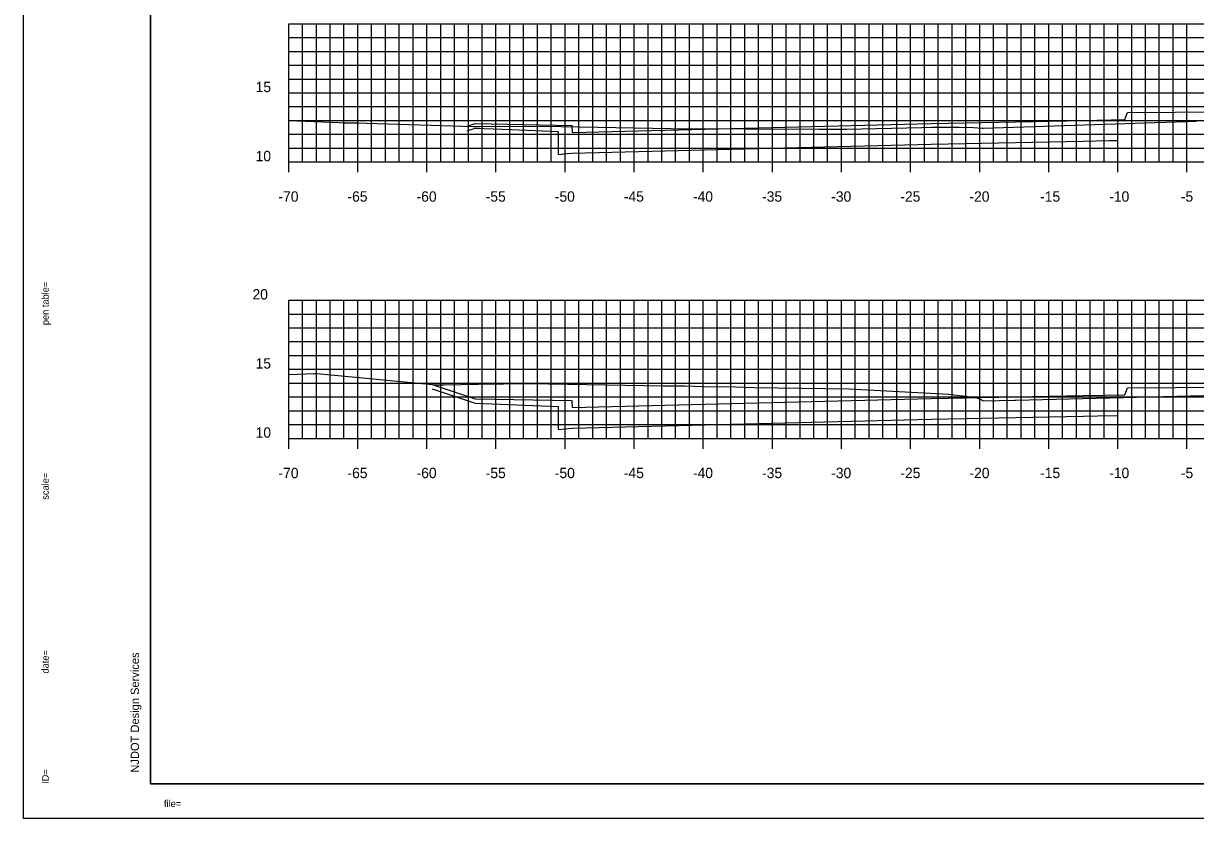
# Model space of a CAD drawing. Extents: x 40011 to 50684, y 49949 to 72236.
# Drawn here: x 41889.7 to 41974.5, y 68071.1 to 68128.6 of the extents above; entities that cross this region are included whole.
import ezdxf

# ---------------------------------------------------------------- set-up
doc = ezdxf.new("R2010")
doc.units = 0
for name, color, linetype in [('1', 7, 'Continuous'), ('41', 7, 'Continuous'), ('51', 7, 'Continuous'), ('52', 7, 'Continuous'), ('53', 7, 'Continuous'), ('54', 7, 'Continuous'), ('55', 7, 'Continuous'), ('57', 7, 'Continuous'), ('58', 7, 'Continuous'), ('59', 7, 'Continuous')]:
    doc.layers.add(name, color=color, linetype=linetype)

msp = doc.modelspace()

# ---------------------------------------------------------------- linework, layer by layer
at = {"layer": '1'}
for p, q in [((41898.891, 68178.597), (41898.891, 68073.597)), ((41898.891, 68073.597), (42063.891, 68073.597)), ((42064.392, 68071.097), (41889.697, 68071.097))]:
    msp.add_line(p, q, dxfattribs=at)
at = {"layer": '41'}
for points in [[(41889.697, 68181.097), (42064.392, 68181.097), (42064.392, 68071.097), (41889.697, 68071.097)], [(41898.891, 68178.597), (42063.891, 68178.597), (42063.891, 68073.597), (41898.891, 68073.597)]]:
    msp.add_lwpolyline(points, close=True, dxfattribs=at)
at = {"layer": '51'}
for p, q in [((41908.891, 68118.597), (41908.891, 68128.597)), ((41908.891, 68128.597), (41909.641, 68128.597)), ((41908.891, 68123.597), (41909.641, 68123.597)), ((41908.891, 68118.597), (41909.641, 68118.597)), ((41908.891, 68098.597), (41908.891, 68108.597)), ((41908.891, 68108.597), (41909.641, 68108.597)), ((41908.891, 68103.597), (41909.641, 68103.597)), ((41908.891, 68098.597), (41909.641, 68098.597))]:
    msp.add_line(p, q, dxfattribs=at)
at = {"layer": '52'}
for p, q in [((41908.891, 68118.597), (42048.891, 68118.597)), ((41908.891, 68117.847), (41908.891, 68118.597)), ((41913.891, 68117.847), (41913.891, 68118.597)), ((41918.891, 68117.847), (41918.891, 68118.597)), ((41923.891, 68117.847), (41923.891, 68118.597)), ((41928.891, 68117.847), (41928.891, 68118.597)), ((41933.891, 68117.847), (41933.891, 68118.597)), ((41938.891, 68117.847), (41938.891, 68118.597)), ((41943.891, 68117.847), (41943.891, 68118.597)), ((41948.891, 68117.847), (41948.891, 68118.597)), ((41953.891, 68117.847), (41953.891, 68118.597)), ((41958.891, 68117.847), (41958.891, 68118.597)), ((41963.891, 68117.847), (41963.891, 68118.597)), ((41968.891, 68117.847), (41968.891, 68118.597)), ((41973.891, 68117.847), (41973.891, 68118.597)), ((41908.891, 68098.597), (42048.891, 68098.597)), ((41908.891, 68097.847), (41908.891, 68098.597)), ((41913.891, 68097.847), (41913.891, 68098.597)), ((41918.891, 68097.847), (41918.891, 68098.597)), ((41923.891, 68097.847), (41923.891, 68098.597)), ((41928.891, 68097.847), (41928.891, 68098.597)), ((41933.891, 68097.847), (41933.891, 68098.597)), ((41938.891, 68097.847), (41938.891, 68098.597)), ((41943.891, 68097.847), (41943.891, 68098.597)), ((41948.891, 68097.847), (41948.891, 68098.597)), ((41953.891, 68097.847), (41953.891, 68098.597)), ((41958.891, 68097.847), (41958.891, 68098.597)), ((41963.891, 68097.847), (41963.891, 68098.597)), ((41968.891, 68097.847), (41968.891, 68098.597)), ((41973.891, 68097.847), (41973.891, 68098.597))]:
    msp.add_line(p, q, dxfattribs=at)
at = {"layer": '53'}
for p, q in [((41908.891, 68127.597), (42048.891, 68127.597)), ((41908.891, 68126.597), (42048.891, 68126.597)), ((41908.891, 68125.597), (42048.891, 68125.597)), ((41908.891, 68124.597), (42048.891, 68124.597)), ((41908.891, 68122.597), (42048.891, 68122.597)), ((41908.891, 68121.597), (42048.891, 68121.597)), ((41908.891, 68120.597), (42048.891, 68120.597)), ((41908.891, 68119.597), (42048.891, 68119.597)), ((41908.891, 68107.597), (42048.891, 68107.597)), ((41908.891, 68106.597), (42048.891, 68106.597)), ((41908.891, 68105.597), (42048.891, 68105.597)), ((41908.891, 68104.597), (42048.891, 68104.597)), ((41908.891, 68102.597), (42048.891, 68102.597)), ((41908.891, 68101.597), (42048.891, 68101.597)), ((41908.891, 68100.597), (42048.891, 68100.597)), ((41908.891, 68099.597), (42048.891, 68099.597))]:
    msp.add_line(p, q, dxfattribs=at)
at = {"layer": '54'}
for p, q in [((41909.891, 68118.597), (41909.891, 68128.597)), ((41910.891, 68118.597), (41910.891, 68128.597)), ((41911.891, 68118.597), (41911.891, 68128.597)), ((41912.891, 68118.597), (41912.891, 68128.597)), ((41914.891, 68118.597), (41914.891, 68128.597)), ((41915.891, 68118.597), (41915.891, 68128.597)), ((41916.891, 68118.597), (41916.891, 68128.597)), ((41917.891, 68118.597), (41917.891, 68128.597)), ((41919.891, 68118.597), (41919.891, 68128.597)), ((41920.891, 68118.597), (41920.891, 68128.597)), ((41921.891, 68118.597), (41921.891, 68128.597)), ((41922.891, 68118.597), (41922.891, 68128.597)), ((41924.891, 68118.597), (41924.891, 68128.597)), ((41925.891, 68118.597), (41925.891, 68128.597)), ((41926.891, 68118.597), (41926.891, 68128.597)), ((41927.891, 68118.597), (41927.891, 68128.597)), ((41929.891, 68118.597), (41929.891, 68128.597)), ((41930.891, 68118.597), (41930.891, 68128.597)), ((41931.891, 68118.597), (41931.891, 68128.597)), ((41932.891, 68118.597), (41932.891, 68128.597)), ((41934.891, 68118.597), (41934.891, 68128.597)), ((41935.891, 68118.597), (41935.891, 68128.597)), ((41936.891, 68118.597), (41936.891, 68128.597)), ((41937.891, 68118.597), (41937.891, 68128.597)), ((41939.891, 68118.597), (41939.891, 68128.597)), ((41940.891, 68118.597), (41940.891, 68128.597)), ((41941.891, 68118.597), (41941.891, 68128.597)), ((41942.891, 68118.597), (41942.891, 68128.597)), ((41944.891, 68118.597), (41944.891, 68128.597)), ((41945.891, 68118.597), (41945.891, 68128.597)), ((41946.891, 68118.597), (41946.891, 68128.597)), ((41947.891, 68118.597), (41947.891, 68128.597)), ((41949.891, 68118.597), (41949.891, 68128.597)), ((41950.891, 68118.597), (41950.891, 68128.597)), ((41951.891, 68118.597), (41951.891, 68128.597)), ((41952.891, 68118.597), (41952.891, 68128.597)), ((41954.891, 68118.597), (41954.891, 68128.597)), ((41955.891, 68118.597), (41955.891, 68128.597)), ((41956.891, 68118.597), (41956.891, 68128.597)), ((41957.891, 68118.597), (41957.891, 68128.597)), ((41959.891, 68118.597), (41959.891, 68128.597)), ((41960.891, 68118.597), (41960.891, 68128.597)), ((41961.891, 68118.597), (41961.891, 68128.597)), ((41962.891, 68118.597), (41962.891, 68128.597)), ((41964.891, 68118.597), (41964.891, 68128.597)), ((41965.891, 68118.597), (41965.891, 68128.597)), ((41966.891, 68118.597), (41966.891, 68128.597)), ((41967.891, 68118.597), (41967.891, 68128.597)), ((41969.891, 68118.597), (41969.891, 68128.597)), ((41970.891, 68118.597), (41970.891, 68128.597)), ((41971.891, 68118.597), (41971.891, 68128.597)), ((41972.891, 68118.597), (41972.891, 68128.597)), ((41909.891, 68098.597), (41909.891, 68108.597)), ((41910.891, 68098.597), (41910.891, 68108.597)), ((41911.891, 68098.597), (41911.891, 68108.597)), ((41912.891, 68098.597), (41912.891, 68108.597)), ((41914.891, 68098.597), (41914.891, 68108.597)), ((41915.891, 68098.597), (41915.891, 68108.597)), ((41916.891, 68098.597), (41916.891, 68108.597)), ((41917.891, 68098.597), (41917.891, 68108.597)), ((41919.891, 68098.597), (41919.891, 68108.597)), ((41920.891, 68098.597), (41920.891, 68108.597)), ((41921.891, 68098.597), (41921.891, 68108.597)), ((41922.891, 68098.597), (41922.891, 68108.597)), ((41924.891, 68098.597), (41924.891, 68108.597)), ((41925.891, 68098.597), (41925.891, 68108.597)), ((41926.891, 68098.597), (41926.891, 68108.597)), ((41927.891, 68098.597), (41927.891, 68108.597)), ((41929.891, 68098.597), (41929.891, 68108.597)), ((41930.891, 68098.597), (41930.891, 68108.597)), ((41931.891, 68098.597), (41931.891, 68108.597)), ((41932.891, 68098.597), (41932.891, 68108.597)), ((41934.891, 68098.597), (41934.891, 68108.597)), ((41935.891, 68098.597), (41935.891, 68108.597)), ((41936.891, 68098.597), (41936.891, 68108.597)), ((41937.891, 68098.597), (41937.891, 68108.597)), ((41939.891, 68098.597), (41939.891, 68108.597)), ((41940.891, 68098.597), (41940.891, 68108.597)), ((41941.891, 68098.597), (41941.891, 68108.597)), ((41942.891, 68098.597), (41942.891, 68108.597)), ((41944.891, 68098.597), (41944.891, 68108.597)), ((41945.891, 68098.597), (41945.891, 68108.597)), ((41946.891, 68098.597), (41946.891, 68108.597)), ((41947.891, 68098.597), (41947.891, 68108.597)), ((41949.891, 68098.597), (41949.891, 68108.597)), ((41950.891, 68098.597), (41950.891, 68108.597)), ((41951.891, 68098.597), (41951.891, 68108.597)), ((41952.891, 68098.597), (41952.891, 68108.597)), ((41954.891, 68098.597), (41954.891, 68108.597)), ((41955.891, 68098.597), (41955.891, 68108.597)), ((41956.891, 68098.597), (41956.891, 68108.597)), ((41957.891, 68098.597), (41957.891, 68108.597)), ((41959.891, 68098.597), (41959.891, 68108.597)), ((41960.891, 68098.597), (41960.891, 68108.597)), ((41961.891, 68098.597), (41961.891, 68108.597)), ((41962.891, 68098.597), (41962.891, 68108.597)), ((41964.891, 68098.597), (41964.891, 68108.597)), ((41965.891, 68098.597), (41965.891, 68108.597)), ((41966.891, 68098.597), (41966.891, 68108.597)), ((41967.891, 68098.597), (41967.891, 68108.597)), ((41969.891, 68098.597), (41969.891, 68108.597)), ((41970.891, 68098.597), (41970.891, 68108.597)), ((41971.891, 68098.597), (41971.891, 68108.597)), ((41972.891, 68098.597), (41972.891, 68108.597))]:
    msp.add_line(p, q, dxfattribs=at)
at = {"layer": '55'}
for p, q in [((41908.891, 68128.597), (42048.891, 68128.597)), ((41908.891, 68118.597), (41908.891, 68128.597)), ((41913.891, 68118.597), (41913.891, 68128.597)), ((41918.891, 68118.597), (41918.891, 68128.597)), ((41923.891, 68118.597), (41923.891, 68128.597)), ((41928.891, 68118.597), (41928.891, 68128.597)), ((41933.891, 68118.597), (41933.891, 68128.597)), ((41938.891, 68118.597), (41938.891, 68128.597)), ((41943.891, 68118.597), (41943.891, 68128.597)), ((41948.891, 68118.597), (41948.891, 68128.597)), ((41953.891, 68118.597), (41953.891, 68128.597)), ((41958.891, 68118.597), (41958.891, 68128.597)), ((41963.891, 68118.597), (41963.891, 68128.597)), ((41968.891, 68118.597), (41968.891, 68128.597)), ((41973.891, 68118.597), (41973.891, 68128.597)), ((41908.891, 68123.597), (42048.891, 68123.597)), ((41908.891, 68118.597), (42048.891, 68118.597)), ((41908.891, 68108.597), (42048.891, 68108.597)), ((41908.891, 68098.597), (41908.891, 68108.597)), ((41913.891, 68098.597), (41913.891, 68108.597)), ((41918.891, 68098.597), (41918.891, 68108.597)), ((41923.891, 68098.597), (41923.891, 68108.597)), ((41928.891, 68098.597), (41928.891, 68108.597)), ((41933.891, 68098.597), (41933.891, 68108.597)), ((41938.891, 68098.597), (41938.891, 68108.597)), ((41943.891, 68098.597), (41943.891, 68108.597)), ((41948.891, 68098.597), (41948.891, 68108.597)), ((41953.891, 68098.597), (41953.891, 68108.597)), ((41958.891, 68098.597), (41958.891, 68108.597)), ((41963.891, 68098.597), (41963.891, 68108.597)), ((41968.891, 68098.597), (41968.891, 68108.597)), ((41973.891, 68098.597), (41973.891, 68108.597)), ((41908.891, 68103.597), (42048.891, 68103.597)), ((41908.891, 68098.597), (42048.891, 68098.597))]:
    msp.add_line(p, q, dxfattribs=at)
at = {"layer": '57'}
for points in [[(41908.891, 68121.607), (41912.549, 68121.441), (41912.797, 68121.438), (41913.222, 68121.432), (41913.972, 68121.421), (41914.532, 68121.412), (41922.258, 68121.162), (41922.449, 68121.159), (41922.757, 68121.155), (41927.284, 68121.175), (41936.544, 68121.019), (41947.26, 68120.967), (41949.249, 68120.966), (41954.711, 68121.095), (41955.427, 68121.11), (41955.84, 68121.113), (41956.519, 68121.116), (41957.412, 68121.106), (41958.436, 68121.091), (41959.064, 68121.039), (41959.153, 68121.029), (41974.554, 68121.546)], [(41908.891, 68103.214), (41910.747, 68103.299), (41910.96, 68103.29), (41919.544, 68102.48), (41920.148, 68102.482), (41922.608, 68102.517), (41926.315, 68102.579), (41935.991, 68102.41), (41937.099, 68102.401), (41937.566, 68102.394), (41938.273, 68102.38), (41938.923, 68102.362), (41941.236, 68102.323), (41942.57, 68102.282), (41949.44, 68102.175), (41956.204, 68101.825), (41956.63, 68101.809), (41958.25, 68101.605), (41958.548, 68101.584), (41958.556, 68101.585), (41959.031, 68101.377), (41959.036, 68101.375), (41959.037, 68101.374), (41959.19, 68101.307), (41961.41, 68101.361), (41961.496, 68101.363), (41980.931, 68101.835)]]:
    msp.add_lwpolyline(points, dxfattribs=at)
at = {"layer": '58'}
for points in [[(41921.796, 68120.847), (41921.938, 68120.894), (41922.382, 68121.042), (41924.978, 68120.94), (41928.386, 68120.807), (41928.396, 68119.138), (41929.029, 68119.197), (41929.391, 68119.231), (41955.391, 68119.881), (41966.391, 68120.101), (41968.285, 68120.139), (41968.891, 68120.151)], [(41919.277, 68102.175), (41920.36, 68101.814), (41922.381, 68101.14), (41928.386, 68100.904), (41928.391, 68100.05), (41928.396, 68099.235), (41929.392, 68099.329), (41955.391, 68099.979), (41966.392, 68100.199), (41966.406, 68100.199), (41967.421, 68100.22), (41968.891, 68100.249)]]:
    msp.add_lwpolyline(points, dxfattribs=at)
at = {"layer": '59'}
for points in [[(41921.796, 68121.177), (41922.382, 68121.372), (41929.382, 68121.232), (41929.392, 68120.732), (41955.392, 68121.382), (41966.392, 68121.602), (41969.391, 68121.662), (41969.582, 68122.164), (41976.506, 68122.217), (41981.202, 68122.254), (41981.391, 68121.755), (41984.392, 68121.71), (41995.392, 68121.49), (42010.392, 68121.115), (42010.402, 68121.615), (42017.402, 68121.755), (42017.69, 68121.851)], [(41919.276, 68102.505), (41922.382, 68101.47), (41929.382, 68101.33), (41929.392, 68100.83), (41955.392, 68101.48), (41966.392, 68101.7), (41969.391, 68101.76), (41969.582, 68102.261), (41976.506, 68102.315), (41981.202, 68102.351), (41981.391, 68101.852), (41984.392, 68101.807), (41995.392, 68101.587), (42010.392, 68101.212), (42010.402, 68101.712), (42017.402, 68101.852), (42017.513, 68101.889)]]:
    msp.add_lwpolyline(points, dxfattribs=at)

# ---------------------------------------------------------------- texts
at = {"layer": '1'}
for s, height, rotation, p in [('...................pentable..................', 0.0072, 90, (41891.529, 68110.775)), ('pen table=', 0.5, 90, (41891.529, 68106.791)), ('scale=', 0.5, 90, (41891.529, 68094.163)), ('......scale......', 0.0072, 90, (41891.529, 68096.608)), ('date=', 0.5, 90, (41891.529, 68081.587)), ('.......time......', 0.0072, 90, (41891.529, 68083.775)), ('NJDOT Design Services', 0.6, 90, (41898.058, 68074.419)), ('............who............', 0.0072, 90, (41891.529, 68074.93)), ('ID=', 0.5, 90, (41891.529, 68073.601)), ('file=', 0.5, 360, (41899.865, 68071.93)), ('...................bob..................', 0.0072, 360, (41901.53, 68071.93))]:
    msp.add_text(s, height=height, rotation=rotation, dxfattribs=at).set_placement(p)
at = {"layer": '51'}
for s, height, p in [('15', 0.75, (41906.498, 68123.647)), ('10', 0.75, (41906.498, 68118.647)), ('-', 0.0001, (41908.891, 68118.597)), ('20', 0.75, (41906.271, 68108.647)), ('15', 0.75, (41906.498, 68103.647)), ('10', 0.75, (41906.498, 68098.647)), ('-', 0.0001, (41908.891, 68098.597))]:
    msp.add_text(s, height=height, dxfattribs=at).set_placement(p)
at = {"layer": '52'}
for s, p in [('-70', (41908.152, 68115.722)), ('-65', (41913.146, 68115.722)), ('-60', (41918.146, 68115.722)), ('-55', (41923.148, 68115.722)), ('-50', (41928.148, 68115.722)), ('-45', (41933.143, 68115.722)), ('-40', (41938.143, 68115.722)), ('-35', (41943.148, 68115.722)), ('-30', (41948.148, 68115.722)), ('-25', (41953.152, 68115.722)), ('-20', (41958.152, 68115.722)), ('-15', (41963.266, 68115.722)), ('-10', (41968.266, 68115.722)), ('-5', (41973.45, 68115.722)), ('-70', (41908.152, 68095.722)), ('-65', (41913.146, 68095.722)), ('-60', (41918.146, 68095.722)), ('-55', (41923.148, 68095.722)), ('-50', (41928.148, 68095.722)), ('-45', (41933.143, 68095.722)), ('-40', (41938.143, 68095.722)), ('-35', (41943.148, 68095.722)), ('-30', (41948.148, 68095.722)), ('-25', (41953.152, 68095.722)), ('-20', (41958.152, 68095.722)), ('-15', (41963.266, 68095.722)), ('-10', (41968.266, 68095.722)), ('-5', (41973.45, 68095.722))]:
    msp.add_text(s, height=0.75, dxfattribs=at).set_placement(p)

doc.saveas('drawing.dxf')
